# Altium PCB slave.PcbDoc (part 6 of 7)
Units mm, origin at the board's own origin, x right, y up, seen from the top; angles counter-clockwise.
Board outline 160 x 100 mm, 6 copper layers (Top, FUSED_VBAT-, Signals1, Signals2, SUPPLY, Bottom), stack 1.67 mm thick; 597 components, 381 nets, 1695 pads, 3028 vias.
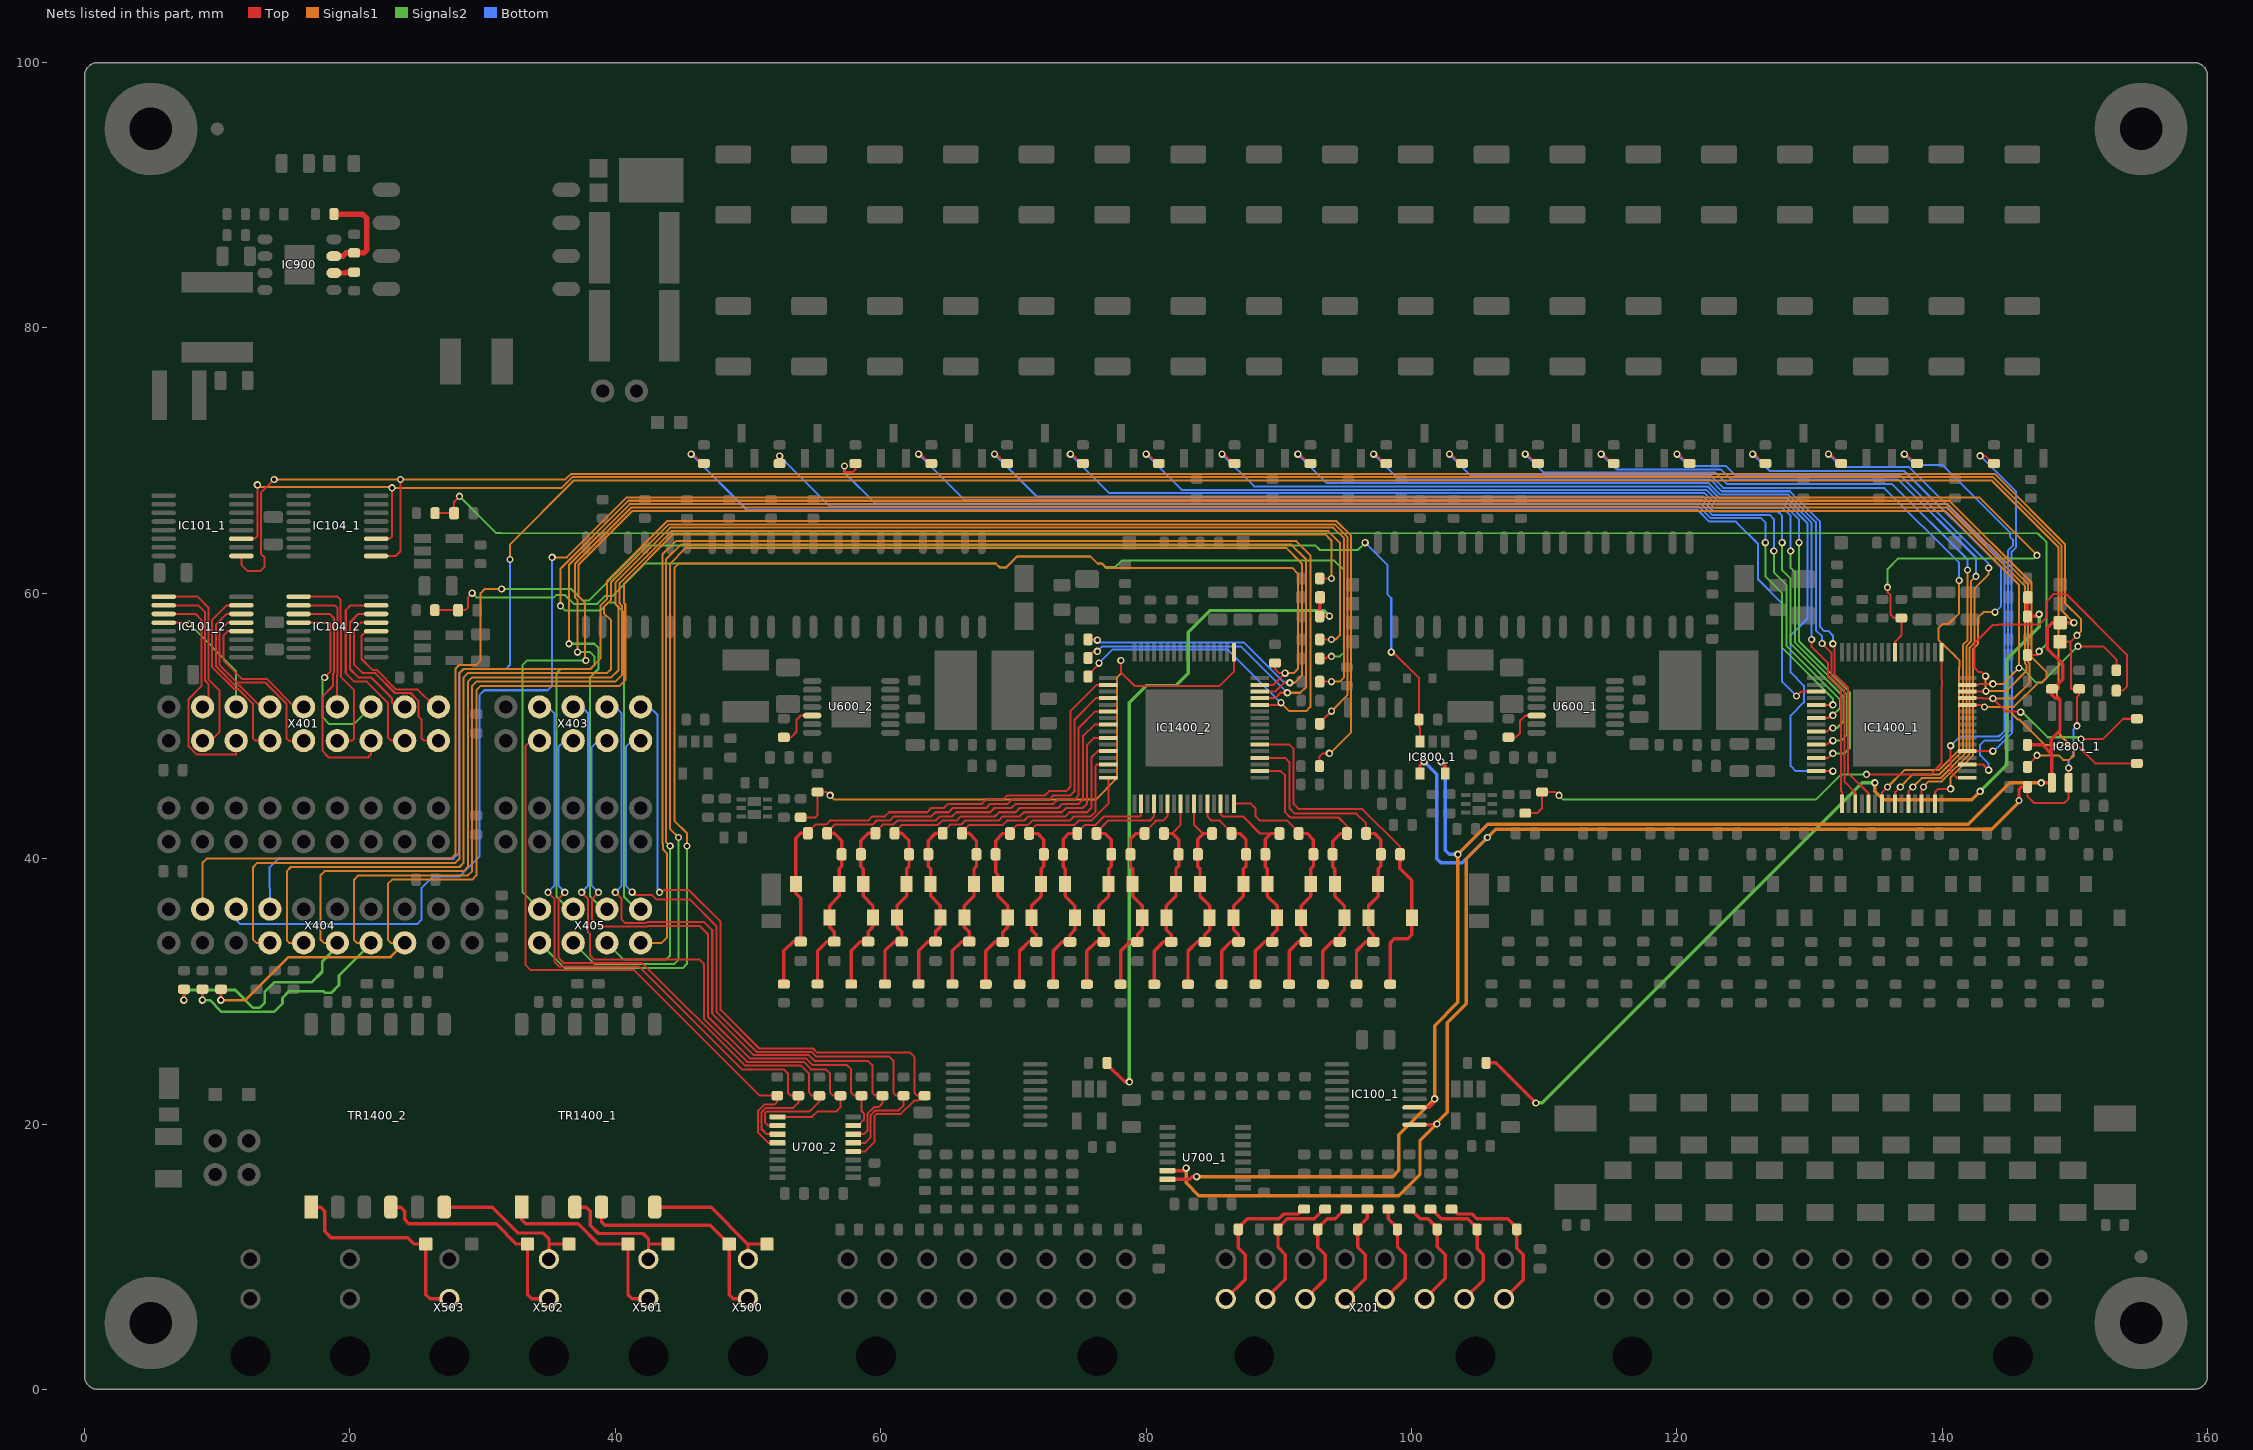
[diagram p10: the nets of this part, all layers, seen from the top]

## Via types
v1: diameter 0.55, hole 0.3, Top to Bottom, tented both sides, 2990 vias
v2: diameter 0.75, hole 0.5, Top to Bottom, tented both sides, 22 vias
v3: diameter 0.65, hole 0.4, Top to Bottom, tented both sides, 16 vias

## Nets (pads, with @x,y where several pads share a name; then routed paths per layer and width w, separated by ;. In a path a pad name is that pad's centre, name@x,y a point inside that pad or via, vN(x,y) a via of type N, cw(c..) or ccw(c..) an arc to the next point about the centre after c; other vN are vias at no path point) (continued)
PRIMARY-GPIO5-OPT: R1416_1.1 X404.13 | length 185.9
  Top w0.152: R1416_1.1@146.433,46.915 146.433,47.015 147.161,47.744 v1(147.161,47.784)
  Signals1 w0.152: v1(32.067,62.547) 32.067,63.691 36.876,68.499 143.748,68.499 148.76,63.487 148.76,52.77 148.671,52.681 148.671,52.221 148.887,52.005 148.887,49.318 149.906,48.299 149.843,48.299 149.906,48.236 149.906,47.776 149.582,47.452 149.122,47.452 148.79,47.784 v1(147.161,47.784)
  Bottom w0.152: X404.13@13.97,36.195 13.95,39.358 14.585,39.993 27.801,39.993 28.237,40.429 28.237,53.963 28.555,54.28 31.73,54.28 32.047,54.597 v1(32.067,62.547)
PRIMARY-GPIO6: IC1400_1.44 R1421_1.1 X405.1 | length 173.1
  Top w0.152: IC1400_1.44@141.958,51.598 143.03,51.598 v1(143.192,51.435) ; v1(148.844,48.578) 150.135,48.578 151.534,47.179 R1421_1.1@154.686,47.179
  Signals2 w0.152: v1(35.877,59.055) 36.241,58.691 38.857,58.691 39.458,59.292 39.917,59.292 40.64,58.569 40.64,37.148 41.593,36.195 X405.1@41.91,36.195
  Signals1 w0.152: v1(35.877,59.055) 35.877,61.869 40.984,66.975 140.548,66.975 146.746,60.778 146.746,55.186 147.854,54.078 147.854,53.618 147.53,53.294 147.272,53.294 145.414,51.435 144.748,51.435 ; v1(143.192,51.435) 144.748,51.435 ; v1(148.844,48.578) 147.744,48.578 145.832,50.49 145.693,50.49 144.748,51.435
PRIMARY-GPIO7: IC1400_1.45 R1422_1.1 X405.3 | length 168.9
  Top w0.152: IC1400_1.45@141.908,52.097 143.061,52.097 143.088,52.071 143.547,52.071 ; IC1400_1.45@141.958,52.097 IC1400_1.45@141.984,52.071 ; 143.548,52.071 v1@143.826,52.071 ; v1(143.827,52.07) 144.792,51.106 145.627,51.106 145.806,50.927 v1(145.923,51.044) ; v1(150.475,49.022) 152.148,49.022 153.67,50.544 R1422_1.1@154.686,50.544
  Signals2 w0.152: v1(36.512,56.197) 38.417,56.197 38.735,55.88 38.735,54.292 38.1,53.657 38.1,37.148 39.052,36.195 X405.3@39.37,36.195 ; v1(145.923,51.044) 146.062,51.044 147.957,49.149 150.348,49.149 v1(150.475,49.022)
  Signals1 w0.152: v1(36.512,56.197) 36.512,62.145 41.089,66.721 140.443,66.721 146.492,60.673 146.492,54.821 146.604,54.708 146.604,53.259 145.415,52.07 v1(143.827,52.07)
PRIMARY-GPIO8: IC1400_1.46 R1423_1.1 X405.5 | length 178.4
  Top w0.152: IC1400_1.46@141.958,52.598 143.29,52.598 v1(143.317,52.625) ; v1(143.29,53.751) 142.985,54.056 142.772,54.056 142.448,54.38 142.448,56.237 143.823,57.612 144.248,57.612 144.269,57.633 147.317,57.633 147.874,58.19 147.874,59.394 148.425,59.944 149.35,59.944 153.924,55.37 153.924,52.959 153.63,52.665 R1423_1.1@153.132,52.665
  Signals2 w0.152: X405.5@36.83,36.195 36.512,36.195 35.56,37.148 35.56,53.975 35.877,54.292 38.1,54.292 38.417,54.61 38.417,55.245 38.1,55.562 v1(37.148,55.562)
  Signals1 w0.152: v1(37.148,55.562) 37.148,59.499 36.974,59.673 36.974,62.247 41.194,66.467 140.338,66.467 146.238,60.568 146.238,54.716 146.35,54.603 146.35,54.143 144.832,52.625 v1(143.317,52.625) ; v1@143.29,52.598 143.29,52.934 143.273,52.951 143.273,53.41 143.29,53.427 v1(143.29,53.751)
PRIMARY-GPIO9: IC1400_1.47 R1424_1.1 X405.7 | length 164.7
  Top w0.152: IC1400_1.47@141.908,53.097 142.709,53.097 142.792,53.18 v1(143.827,53.18) ; v1(150.241,56.007) 152.144,56.007 153.132,55.019 R1424_1.1@153.132,54.199
  Signals2 w0.152: X405.7@34.29,36.195 33.02,37.465 33.02,54.61 33.337,54.927 v1(37.782,54.927) ; v1(145.796,54.373) 145.991,54.373 147.07,53.294 147.53,53.294 150.241,56.005 v1(150.241,56.007)
  Signals1 w0.152: v1(37.782,54.927) 37.702,55.008 37.702,59.304 37.228,59.778 37.228,62.142 41.299,66.213 140.232,66.213 145.796,60.65 v1(145.796,54.373) 144.603,53.18 v1(143.827,53.18)
PRIMARY-IN+: TP1405_1.1 TR1400_1.4 X500.1 | length 16.8
  Top w0.254: TR1400_1.4@38.961,13.738 38.961,12.633 39.211,12.383 47.161,12.383 TP1405_1.1@48.59,10.954 48.59,7.131 48.903,6.818 X500.1@50,6.818
PRIMARY-IN-: TP1404_1.1 TR1400_1.6 X500.2 | length 10.7
  Top w0.254: TR1400_1.6@43.068,13.738 47.216,13.738 50,10.954 ; X500.2@50,9.815 50,10.954 ; TP1404_1.1@51.435,10.954 50,10.954
PRIMARY-LTC-DRIVE: IC1400_1.49 R605_1.1 R610_1.2 | length 42.6
  Top w0.152: R605_1.1@108.585,43.432 109.472,43.432 109.855,43.815 R610_1.2@109.855,45.02 110.872,45.02 v1(111.125,44.767) ; v1(134.302,46.355) 139.14,46.355 139.958,47.173 139.958,52.981 140.012,53.035 140.012,53.495 139.958,53.549 IC1400_1.49@139.958,55.547 ; IC1400_1.49@139.958,55.598 IC1400_1.49@139.993,55.562
  Signals2 w0.152: v1(111.125,44.767) 111.443,44.45 111.76,44.45 130.493,44.45 132.398,46.355 v1(134.302,46.355)
PRIMARY-MUX-DATA_TEMP: C106_1.2 R108_1.2 R1409_1.1 | length 67.2
  Top w0.254: R108_1.2@105.634,24.606 106.362,24.606 v1(109.379,21.59) ; R1409_1.1@146.433,58.261 146.433,59.088 146.457,59.113 C106_1.2@146.457,59.69 ; R1409_1.1@146.483,58.261 147.154,58.261 147.173,58.281 v1(147.32,58.42)
  Signals2 w0.254: v1(109.379,21.59) 109.855,21.59 133.985,45.72 v1(134.938,45.72) ; v1(142.875,45.077) 144.882,47.084 144.882,55.029 147.32,57.468 v1(147.32,58.42)
  Signals1 w0.254: v1(134.938,45.72) 134.938,45.085 135.572,44.45 142.248,44.45 v1(142.875,45.077)
PRIMARY-MUX-DATA_USER: C107_1.2 R109_1.2 R1411_1.1 | length 133.5
  Top w0.152: R109_1.2@26.417,66.04 C107_1.2@27.85,66.04 27.85,66.903 v1(28.258,67.31) ; R1411_1.1@146.433,55.34 147.192,55.34 147.32,55.468 v1(147.32,55.626)
  Signals2 w0.152: v1(28.258,67.31) 31.039,64.528 31.432,64.528 147.191,64.516 147.874,63.833 147.874,56.18 v1(147.32,55.626)
PRIMARY-OUT+: TP1406_1.1 TR1400_1.1 X501.1 | length 15.2
  Top w0.254: TR1400_1.1@32.941,13.738 32.941,12.779 33.235,12.485 37.204,12.485 38.735,10.954 TP1406_1.1@40.957,10.954 40.957,7.144 41.283,6.818 X501.1@42.5,6.818
PRIMARY-OUT-: TP1407_1.1 TR1400_1.3 X501.2 | length 10.4
  Top w0.254: TR1400_1.3@37.048,13.434 37.048,13.738 37.809,13.738 38.112,13.434 38.112,12.37 38.735,11.747 42.088,11.747 42.5,11.335 42.5,10.954 ; X501.2@42.5,9.815 42.5,10.954 ; TP1407_1.1@43.974,10.954 42.5,10.954
PRIMARY-S1: IC1400_1.37 R1517.2 | length 27.4
  Top w0.152: IC1400_1.37@141.958,48.097 143.824,48.097 v1(143.827,48.101) ; v1(142.875,70.358) 143.245,70.358 143.818,69.785 R1517.2@143.918,69.785 ; R1517.2@144.045,69.785 R1517.2@144.145,69.785
  Bottom w0.152: v1(142.875,70.358) 145.588,67.645 145.588,63.483 145.242,63.136 145.242,54.143 145.287,54.098 145.287,49.487 143.901,48.101 v1(143.827,48.101)
PRIMARY-S2: IC1400_1.35 R1516.2 | length 33.4
  Top w0.152: v1(137.16,70.485) 137.313,70.485 138.013,69.785 R1516.2@138.112,69.785 ; IC1400_1.35@141.908,47.097 143.085,47.097 v1(143.51,46.672)
  Bottom w0.152: v1(137.16,70.485) 137.958,69.687 140.017,69.687 145.115,64.59 145.115,64.267 145.334,64.047 145.334,63.588 144.953,63.207 144.953,49.513 144.399,48.959 144.336,48.959 144.336,48.895 143.192,48.895 142.875,48.578 142.875,47.784 143.51,47.149 v1(143.51,46.672)
PRIMARY-S3: IC1400_1.33 R1515.2 | length 38.5
  Top w0.152: v1(131.445,70.485) 131.598,70.485 132.298,69.785 R1515.2@132.398,69.785 ; v1(140.653,48.509) 140.653,46.551 141.106,46.097 IC1400_1.33@141.908,46.097
  Bottom w0.152: v1(131.445,70.485) 132.398,69.532 137.477,69.532 144.699,62.311 144.699,49.618 144.375,49.293 144.294,49.293 144.294,49.212 141.356,49.212 v1(140.653,48.509)
PRIMARY-S4: IC1400_1.31 R1514.2 | length 44.5
  Top w0.152: v1(125.73,70.485) 125.883,70.485 126.583,69.785 R1514.2@126.682,69.785 ; IC1400_1.31@139.457,44.097 139.457,45.001 139.721,45.265 v1(140.653,45.265)
  Signals1 w0.152: v1(140.653,45.265) 140.653,46.125 142.335,47.807 142.335,55.806 142.716,56.187 142.716,58.179 143.122,58.584 143.981,58.584 v1(143.986,58.579)
  Bottom w0.152: v1(125.73,70.485) 127,69.215 137.16,69.215 144.445,61.93 144.445,59.038 v1(143.986,58.579)
PRIMARY-S5: IC1400_1.29 R1513.2 | length 48.9
  Top w0.152: v1(120.015,70.485) 120.168,70.485 120.868,69.785 R1513.2@120.968,69.785 ; IC1400_1.29@138.457,44.097 138.457,45.265 v1(138.595,45.402)
  Signals1 w0.152: v1(138.595,45.402) 139.012,45.819 139.988,45.819 142.081,47.913 142.081,55.911 142.43,56.261 142.43,60.357 143.51,61.436 v1(143.51,61.912)
  Bottom w0.152: v1(120.015,70.485) 120.903,69.597 123.709,69.597 124.409,68.897 136.835,68.897 143.51,62.223 v1(143.51,61.912)
PRIMARY-S6: IC1400_1.27 R1512.2 | length 54.2
  Top w0.152: v1(114.303,70.485) 114.453,70.485 115.153,69.785 R1512.2@115.252,69.785 ; IC1400_1.27@137.458,44.147 137.458,45.065 v1(137.795,45.402)
  Signals1 w0.152: v1(137.795,45.402) 138.466,46.073 139.883,46.073 141.827,48.018 141.827,56.017 142.177,56.366 142.177,60.896 v1(142.558,61.277)
  Bottom w0.152: v1(114.303,70.485) 115.445,69.343 123.329,69.343 124.091,68.581 131.446,68.581 131.447,68.58 136.674,68.58 142.558,62.697 v1(142.558,61.277)
PRIMARY-S7: IC1400_1.25 R1535.2 | length 59.8
  Top w0.152: v1(108.585,70.485) 108.738,70.485 109.438,69.785 R1535.2@109.537,69.785 ; IC1400_1.25@136.457,44.097 136.457,45.017 136.467,45.017 v1(136.852,45.402)
  Signals1 w0.152: v1(136.852,45.402) 137.805,46.355 139.805,46.355 141.573,48.123 141.573,56.122 141.922,56.471 v1(141.922,61.754)
  Bottom w0.152: v1(108.585,70.485) 109.981,69.089 122.936,69.089 123.775,68.25 136.22,68.25 141.922,62.547 v1(141.922,61.754)
PRIMARY-S8: IC1400_1.23 R1534.2 | length 66.8
  Top w0.152: v1(102.87,70.485) 103.023,70.485 103.723,69.785 R1534.2@103.822,69.785 ; IC1400_1.23@135.457,44.097 135.457,44.97 v1(135.89,45.402)
  Signals1 w0.152: v1(135.89,45.402) 137.16,46.672 139.763,46.672 141.287,48.197 141.287,54.417 141.319,54.449 141.319,54.908 141.019,55.208 141.019,55.238 140.44,55.816 140.411,55.816 139.717,56.51 139.717,57.36 140.042,57.684 140.483,57.684 141.287,58.489 v1(141.287,60.96)
  Bottom w0.152: v1(102.87,70.485) 104.52,68.835 122.617,68.835 123.507,67.945 130.822,67.945 130.835,67.933 135.656,67.933 141.287,62.301 v1(141.287,60.96)
PRIMARY-S9: IC1400_1.21 R1533.2 | length 60
  Top w0.152: v1(97.155,70.485) 97.308,70.485 98.008,69.785 R1533.2@98.108,69.785 ; v1(131.762,56.197) 131.903,56.057 131.903,53.913 132.905,52.91 132.905,46.482 134.457,44.93 IC1400_1.21@134.457,44.097
  Bottom w0.152: v1(97.155,70.485) 99.059,68.581 122.512,68.581 123.402,67.691 128.524,67.691 130.81,65.405 130.81,57.468 131.127,57.15 131.445,57.15 131.777,56.818 131.777,56.212 v1(131.762,56.197)
PRIMARY-S10: IC1400_1.19 R1532.2 | length 64.9
  Top w0.152: v1(91.44,70.485) 91.593,70.485 92.293,69.785 R1532.2@92.392,69.785 ; v1(130.964,56.212) 131.649,55.527 131.649,53.807 132.651,52.805 132.651,45.783 133.457,44.978 IC1400_1.19@133.457,44.097
  Bottom w0.152: v1(91.44,70.485) 93.616,68.309 122.425,68.309 123.297,67.437 128.419,67.437 130.493,65.363 130.493,57.226 130.964,56.755 v1(130.964,56.212)
PRIMARY-S11: IC1400_1.17 R1531.2 | length 70
  Top w0.152: v1(85.725,70.485) 85.878,70.485 86.578,69.785 R1531.2@86.677,69.785 ; v1(130.175,56.515) 130.175,55.971 131.395,54.751 131.395,53.702 132.398,52.7 132.398,45.085 132.457,45.025 IC1400_1.17@132.457,44.097
  Bottom w0.152: v1(85.725,70.485) 88.155,68.055 122.32,68.055 123.192,67.183 128.314,67.183 130.175,65.322 v1(130.175,56.515)
PRIMARY-S12: IC1400_1.15 R1530.2 | length 77.5
  Top w0.152: v1(80.01,70.485) 80.163,70.485 80.863,69.785 R1530.2@80.962,69.785 ; IC1400_1.15@130.457,46.598 v1(131.762,46.598)
  Bottom w0.152: v1(80.01,70.485) 82.694,67.801 122.215,67.801 123.087,66.929 128.208,66.929 129.857,65.28 129.857,58.102 128.588,56.832 128.588,54.038 129.586,53.04 129.586,51.774 128.588,50.775 128.588,46.99 128.98,46.598 v1(131.762,46.598)
PRIMARY-S13: IC1400_1.13 R1553.2 | length 79.9
  Top w0.152: v1(74.295,70.485) 74.448,70.485 75.148,69.785 R1553.2@75.248,69.785 ; IC1400_1.13@130.457,47.598 131.418,47.598 v1(131.762,47.942)
  Signals2 w0.152: v1(129.222,63.817) 129.222,56.366 133.079,52.51 133.079,48.375 132.646,47.942 v1(131.762,47.942)
  Bottom w0.152: v1(74.295,70.485) 77.233,67.547 122.11,67.547 122.981,66.675 128.103,66.675 129.222,65.556 v1(129.222,63.817)
PRIMARY-S14: IC1400_1.11 R1552.2 | length 84.1
  Top w0.152: v1(68.58,70.485) 68.733,70.485 69.433,69.785 R1552.2@69.532,69.785 ; IC1400_1.11@130.457,48.598 131.306,48.598 131.604,48.895 v1(131.762,48.895)
  Signals2 w0.152: v1(128.588,63.182) 128.588,61.912 128.905,61.595 128.905,56.324 132.825,52.404 132.825,49.322 132.398,48.895 v1(131.762,48.895)
  Bottom w0.152: v1(68.58,70.485) 71.772,67.293 122.004,67.293 122.876,66.421 127.998,66.421 128.588,65.831 v1(128.588,63.182)
PRIMARY-S15: IC1400_1.9 R1551.2 | length 88.1
  Top w0.152: v1(62.865,70.485) 63.018,70.485 63.718,69.785 R1551.2@63.817,69.785 ; IC1400_1.9@130.457,49.598 131.354,49.598 131.604,49.847 v1(131.762,49.847)
  Signals2 w0.152: v1(127.953,63.817) 127.953,61.744 128.588,61.109 128.588,56.197 132.571,52.214 132.571,50.338 132.08,49.847 v1(131.762,49.847)
  Bottom w0.152: v1(62.865,70.485) 66.311,67.039 121.899,67.039 122.771,66.167 127.635,66.167 127.953,65.849 v1(127.953,63.817)
PRIMARY-S16: IC1400_1.7 R1550.2 | length 92.3
  Top w0.152: v1(57.277,69.596) 57.277,69.151 57.921,69.151 58.102,69.333 R1550.2@58.102,69.785 ; IC1400_1.7@130.457,50.598 131.401,50.598 131.604,50.8 v1(131.762,50.8)
  Signals2 w0.152: v1(127.317,63.182) 127.317,61.595 128.27,60.642 128.27,56.039 132.317,51.992 132.317,51.354 v1(131.762,50.8)
  Bottom w0.152: v1(57.277,69.596) 57.277,69.088 59.58,66.785 121.794,66.785 122.666,65.913 127,65.913 127.317,65.596 v1(127.317,63.182)
PRIMARY-S17: IC1400_1.5 R1549.2 | length 94.1
  Top w0.152: R1549.2@52.387,69.785 v1(52.387,70.34) ; IC1400_1.5@130.457,51.598 131.759,51.598 v1(131.762,51.594)
  Signals2 w0.152: v1(126.682,63.817) 126.682,61.277 127.953,60.008 127.953,55.88 131.762,52.07 v1(131.762,51.594)
  Bottom w0.152: v1(52.387,70.34) 56.196,66.531 121.689,66.531 122.561,65.659 126.365,65.659 126.682,65.341 v1(126.682,63.817)
PRIMARY-S18: IC1400_1.3 R1548.2 | length 98.7
  Top w0.152: v1(45.72,70.485) 45.873,70.485 46.573,69.785 R1548.2@46.672,69.785 ; v1(129.032,52.254) 129.376,52.598 IC1400_1.3@130.457,52.598
  Bottom w0.152: v1(45.72,70.485) 49.928,66.277 121.584,66.277 122.455,65.405 124.46,65.405 126.128,63.737 126.128,61.048 127.953,59.223 127.953,53.333 v1(129.032,52.254)
PRIMARY-SCL: IC100_1.1 IC101_1.1 IC104_1.1 IC800_1.4 IC801_1.6 R1417_1.1 R1420_1.1 TP1409_1.1 U700_1.14 | length 287.4
  Top w0.152: IC101_1.1@11.786,62.801 IC101_1.1@11.815,62.801 ; IC101_1.1@11.815,62.813 IC101_1.1@11.815,62.801 ; v1(14.287,68.58) 13.886,68.178 13.889,68.175 13.283,67.568 13.283,62.984 13.572,62.695 13.572,62 13.247,61.676 12.3,61.676 11.815,62.161 IC101_1.1@11.815,62.801 ; IC104_1.1@21.946,62.801 IC104_1.1@21.975,62.801 ; IC104_1.1@21.975,62.813 23.443,62.813 23.812,63.182 v1(23.812,68.58) ; R1417_1.1@146.433,45.402 146.433,44.702 146.939,44.196 149.225,44.196 149.542,44.514 IC801_1.6@149.542,45.719 v1(149.542,46.831) ; TP1409_1.1@148.887,56.356 149.701,56.356 ; v1(150.177,50.006) 150.177,52.188 150.336,52.347 R1420_1.1@150.336,52.799 149.701,52.799 149.701,55.763 149.687,55.777 149.687,56.342 149.701,56.356 ; v1(150.177,56.832) 149.701,56.356
  Top w0.254: U700_1.14@81.605,16.488 82.845,16.488 v1(83.026,16.669) ; IC100_1.1@100.239,19.95 101.865,19.95 v1(101.917,20.002) ; IC800_1.4@100.65,46.425 100.65,46.993 v1(100.965,47.307) ; v1(145.8,44.379) 145.8,45.222 145.981,45.402 R1417_1.1@146.433,45.402
  Signals1 w0.152: v1(14.287,68.58) v1(23.812,68.58) 36.238,68.58 36.666,69.007 143.958,69.007 149.268,63.697 149.268,59.244 150.484,58.028 150.484,57.139 v1(150.177,56.832)
  Signals1 w0.254: v1(83.026,16.669) 83.026,15.557 83.979,14.605 99.06,14.605 100.647,16.192 100.647,18.732 v1(101.917,20.002) 101.917,20.099 102.711,20.893 102.711,27.622 104.14,29.051 104.14,40.005 v1(105.727,41.593) 106.362,42.227 106.68,42.227 143.736,42.227 145.8,44.291 v1(145.8,44.379)
  Bottom w0.152: v1(149.542,46.831) 149.542,47.412 149.906,47.776 149.906,49.735 v1(150.177,50.006)
  Bottom w0.254: v1(100.965,47.307) 101.917,46.355 101.917,40.005 102.235,39.688 103.822,39.688 v1(105.727,41.593)
PRIMARY-SDA: IC100_1.3 IC101_1.3 IC104_1.3 IC800_1.5 IC801_1.5 R1415_1.1 R1419_1.1 TP1408_1.1 U700_1.15 | length 273.5
  Top w0.152: IC101_1.3@11.815,64.113 12.842,64.113 13.018,64.288 v1(13.018,68.178) ; IC104_1.3@21.975,64.113 23.002,64.113 23.177,64.288 v1(23.177,67.945)
  Top w0.254: U700_1.15@81.605,15.838 83.306,15.838 83.502,16.034 v1(83.82,16.034) ; IC100_1.3@100.239,21.25 101.357,21.25 101.702,21.595 101.702,21.843 v1(101.759,21.9) ; v1(102.235,47.307) 102.55,46.992 IC800_1.5@102.55,46.425 ; R1415_1.1@146.433,48.578 147.574,48.578 148.239,47.913 ; v1(147.476,45.719) IC801_1.5@148.273,45.719 148.273,47.879 148.239,47.913 ; v1(149.93,57.785) TP1408_1.1@148.907,57.785 148.306,57.785 147.935,57.414 147.935,55.836 149.098,54.673 149.098,53.524 148.372,52.799 R1419_1.1@148.273,52.799 148.273,52.347 148.522,52.097 148.723,52.097 148.887,51.933 148.887,49.634 148.239,48.985 148.239,47.913
  Signals1 w0.152: v1(13.018,68.178) 13.17,68.026 23.097,68.026 v1(23.177,67.945) 35.963,67.945 36.771,68.753 143.853,68.753 149.014,63.592 149.014,58.7 v1(149.93,57.785)
  Signals1 w0.254: v1(83.82,16.034) 98.584,16.034 99.06,16.51 99.06,19.201 v1(101.759,21.9) 101.759,27.416 103.505,29.163 v1(103.505,40.322) 105.766,42.583 106.68,42.583 141.961,42.583 145.096,45.719 v1(147.476,45.719)
  Bottom w0.254: v1(102.235,47.307) 102.552,46.99 102.552,40.64 102.87,40.322 v1(103.505,40.322)
PRIMARY-T-SENSOR_0: R107_1.1 R112_1.2 X201.1 | length 11.6
  Top w0.254: R112_1.2@103.029,13.588 103.129,13.588 103.499,13.217 104.576,13.217 104.934,12.859 107.255,12.859 107.953,12.161 R107_1.1@107.953,12.061 107.953,10.633 108.426,10.16 108.426,8.254 X201.1@106.99,6.818
PRIMARY-T-SENSOR_1: R106_1.1 R113_1.2 X201.2 | length 10.2
  Top w0.254: R113_1.2@101.441,13.588 101.541,13.588 102.27,12.859 104.255,12.859 104.953,12.161 R106_1.1@104.953,12.061 104.953,10.617 105.41,10.16 105.41,8.235 X201.2@103.993,6.818
PRIMARY-T-SENSOR_2: R105_1.1 R114_1.2 X201.3 | length 8.9
  Top w0.254: R114_1.2@99.854,13.588 99.954,13.588 100.683,12.859 101.255,12.859 101.953,12.161 R105_1.1@101.953,12.061 101.953,10.759 102.552,10.16 102.552,8.374 X201.3@100.996,6.818
PRIMARY-T-SENSOR_3: R104_1.1 R115_1.2 X201.4 | length 7.9
  Top w0.254: X201.4@97.999,6.818 99.536,8.355 99.536,10.16 98.953,10.743 R104_1.1@98.953,12.061 98.953,12.161 98.266,12.848 R115_1.2@98.266,13.588
PRIMARY-T-SENSOR_4: R103_1.1 R116_1.2 X201.5 | length 7.9
  Top w0.254: X201.5@95.001,6.818 96.52,8.337 96.52,10.16 95.953,10.727 R103_1.1@95.953,12.061 95.953,12.161 96.679,12.886 R116_1.2@96.679,13.588
PRIMARY-T-SENSOR_5: R102_1.1 R117_1.2 X201.6 | length 8.9
  Top w0.254: X201.6@92.004,6.818 93.504,8.318 93.504,10.16 92.953,10.711 R102_1.1@92.953,12.061 92.953,12.161 93.651,12.859 94.262,12.859 94.991,13.588 R117_1.2@95.091,13.588
PRIMARY-T-SENSOR_6: R101_1.1 R118_1.2 X201.7 | length 10.3
  Top w0.254: X201.7@89.007,6.818 90.487,8.299 90.487,10.16 89.953,10.694 R101_1.1@89.953,12.061 89.953,12.161 90.651,12.859 92.675,12.859 93.404,13.588 R118_1.2@93.504,13.588
PRIMARY-T-SENSOR_7: R100_1.1 R119_1.2 X201.8 | length 11.7
  Top w0.254: X201.8@86.01,6.818 87.471,8.279 87.471,10.16 86.953,10.678 R100_1.1@86.953,12.061 86.953,12.161 87.651,12.859 90.011,12.859 90.369,13.217 91.446,13.217 91.816,13.588 R119_1.2@91.916,13.588
PRIMARY-TEMP-ALERT: IC800_1.3 R800_1.1 X404.17 | length 130.1
  Top w0.152: v1(98.485,55.562) 98.614,55.562 100.582,53.594 R800_1.1@100.582,50.482 100.582,49.931 100.65,49.863 IC800_1.3@100.65,48.825
  Signals2 w0.152: v1(31.432,60.325) 36.681,60.325 37.553,59.453 38.012,59.453 42.169,63.61 92.769,63.61 93.115,63.263 95.966,63.263 v1(96.52,63.817)
  Signals1 w0.152: X404.17@8.89,36.195 8.89,39.688 9.207,40.005 27.622,40.005 27.94,40.322 27.94,54.292 28.258,54.61 29.527,54.61 29.845,54.927 29.845,60.008 30.162,60.325 v1(31.432,60.325)
  Bottom w0.152: v1(96.52,63.817) 98.188,62.149 98.188,59.927 98.485,59.63 v1(98.485,55.562)
PRIMARY-WDT: IC1400_1.56 R1404_1.1 X404.15 | length 184.9
  Top w0.152: v1(135.89,60.452) 135.89,60.092 136.124,59.859 136.124,58.38 136.136,58.38 136.378,58.137 R1404_1.1@136.93,58.137 136.93,56.821 136.458,56.349 IC1400_1.56@136.458,55.547
  Signals2 w0.152: v1(135.89,60.452) 135.89,61.821 136.694,62.626 146.922,62.626 v1(147.161,62.865)
  Signals1 w0.152: v1(35.242,62.706) 36.355,62.706 40.879,67.229 142.797,67.229 v1(147.161,62.865)
  Bottom w0.152: X404.15@11.43,36.195 11.41,35.389 11.727,35.071 25.062,35.071 25.38,35.389 25.38,37.77 26.269,38.659 28.263,38.659 29.761,40.157 29.761,52.312 30.142,52.693 34.905,52.693 35.222,53.01 35.242,53.03 v1(35.242,62.706)
R_FB: IC900.6 R904.1 | length 1.6
  Top w0.406: IC900.6@18.794,84.138 19.703,84.138 19.768,84.203 R904.1@20.32,84.203
R_REF: IC900.7 R902.2 R905.2 | length 7.7
  Top w0.406: IC900.7@18.794,85.407 19.467,85.407 19.72,85.66 R902.2@20.32,85.66 21.06,85.66 21.273,85.873 21.273,88.265 20.955,88.582 R905.2@18.797,88.582
RON_1: R600_1.1 U600_1.5 | length 3.4
  Top w0.152: R600_1.1@107.315,49.147 107.867,49.147 108.186,49.467 108.186,50.401 108.57,50.785 U600_1.5@109.445,50.785
RON_2: R600_2.1 U600_2.5 | length 3.4
  Top w0.152: R600_2.1@52.705,49.147 53.257,49.147 53.657,49.548 53.657,50.482 53.96,50.785 U600_2.5@54.835,50.785
SECONDARY-ANALOG-IN_0: IC104_2.4 X401.1 | length 10.3
  Top w0.152: IC104_2.4@21.975,57.143 21.225,57.143 20.872,56.79 20.872,55.046 21.69,54.229 22.013,54.229 23.5,52.742 25.116,52.742 26.422,51.435 X401.1@26.67,51.435
SECONDARY-ANALOG-IN_1: IC104_2.5 X401.2 | length 14.8
  Top w0.152: IC104_2.5@21.975,57.793 20.804,57.793 20.32,57.309 20.32,54.61 20.955,53.975 21.907,53.975 23.395,52.488 24.566,52.488 25.183,51.871 25.183,50.7 25.4,50.482 25.4,49.054 25.559,48.895 X401.2@26.67,48.895
SECONDARY-ANALOG-IN_2: IC104_2.6 X401.3 | length 11.2
  Top w0.152: IC104_2.6@21.975,58.443 20.647,58.443 20.002,57.798 20.002,54.292 20.637,53.657 21.59,53.657 23.177,52.07 23.177,51.752 23.495,51.435 X401.3@24.13,51.435
SECONDARY-ANALOG-IN_3: IC104_2.7 X401.4 | length 15.2
  Top w0.152: IC104_2.7@21.946,59.093 20.041,59.093 19.685,58.737 19.685,53.975 20.32,53.34 21.273,53.34 22.86,51.752 22.86,49.149 23.114,48.895 X401.4@24.13,48.895
SECONDARY-ANALOG-IN_4: IC104_2.12 X401.5 | length 14.1
  Top w0.152: IC104_2.12@16.125,57.793 18.407,57.793 18.55,57.65 18.55,54.11 v1(18.098,53.657)
  Signals2 w0.152: v1(18.098,53.657) 17.939,53.499 17.939,50.641 18.415,50.165 20.32,50.165 X401.5@21.59,51.435
SECONDARY-ANALOG-IN_5: IC104_2.11 X401.6 | length 18.2
  Top w0.152: IC104_2.11@16.125,58.443 18.463,58.443 18.796,58.109 18.796,57.763 18.804,57.755 18.804,54.005 18.72,53.921 18.72,53.01 17.939,52.229 17.939,48.101 18.415,47.625 21.361,47.625 21.59,47.854 X401.6@21.59,48.895
SECONDARY-ANALOG-IN_6: IC104_2.10 X401.7 | length 10.5
  Top w0.152: IC104_2.10@16.125,59.093 18.854,59.093 19.05,58.896 19.05,57.868 19.058,57.86 19.058,53.9 19.012,53.853 19.012,51.473 X401.7@19.05,51.435
SECONDARY-ANALOG-IN_7: IC104_2.9 X401.8 | length 15.5
  Top w0.152: IC104_2.9@16.125,59.743 19.072,59.743 19.304,59.51 19.304,57.974 19.312,57.966 19.312,53.794 19.304,53.786 19.304,53.721 20.32,52.705 20.32,49.054 20.161,48.895 X401.8@19.05,48.895
SECONDARY-ANALOG-IN_8: IC101_2.4 X401.9 | length 10.9
  Top w0.152: IC101_2.4@11.815,57.143 10.788,57.143 10.477,56.832 10.477,54.927 11.857,53.548 13.73,53.548 15.855,51.423 X401.9@16.51,51.435
SECONDARY-ANALOG-IN_9: IC101_2.5 X401.10 | length 14.7
  Top w0.152: IC101_2.5@11.815,57.793 10.788,57.793 10.16,57.164 10.16,54.61 11.476,53.294 13.6,53.294 15.22,51.674 15.22,49.074 15.413,48.881 X401.10@16.51,48.895
SECONDARY-ANALOG-IN_10: IC101_2.6 X401.11 | length 10.7
  Top w0.152: IC101_2.6@11.815,58.443 10.71,58.443 9.906,57.639 9.906,54.505 11.371,53.04 11.698,53.04 13.315,51.423 X401.11@13.97,51.435
SECONDARY-ANALOG-IN_11: IC101_2.7 X401.12 | length 14.4
  Top w0.152: IC101_2.7@11.786,59.093 10.71,59.093 9.588,57.971 9.588,54.463 11.266,52.786 11.568,52.786 12.68,51.674 12.68,49.074 12.859,48.895 X401.12@13.97,48.895
SECONDARY-ANALOG-IN_12: IC101_2.12 X401.13 | length 9.7
  Top w0.152: IC101_2.12@5.965,57.793 7.772,57.793 v1(7.874,57.691)
  Signals2 w0.152: v1(7.874,57.691) 11.43,54.135 X401.13@11.43,51.435
SECONDARY-ANALOG-IN_13: IC101_2.11 X401.14 | length 17.9
  Top w0.152: IC101_2.11@5.965,58.443 8.359,58.443 8.826,57.975 8.826,53.023 7.837,52.033 7.837,48.459 8.454,47.842 11.418,47.842 11.43,47.854 X401.14@11.43,48.895
SECONDARY-ANALOG-IN_14: IC101_2.10 X401.15 | length 10.8
  Top w0.152: IC101_2.10@5.994,59.093 8.572,59.093 9.08,58.585 9.08,53.425 9.335,53.171 9.335,51.88 X401.15@8.89,51.435 X401.15@8.852,51.473
SECONDARY-ANALOG-IN_15: IC101_2.9 X401.16 | length 15
  Top w0.152: IC101_2.9@5.965,59.743 8.52,59.743 9.335,58.928 9.335,53.53 10.16,52.705 10.16,49.53 9.525,48.895 X401.16@8.89,48.895
SECONDARY-C0: C1311_2.2 IC1400_2.38 R1306_2.2 Z1305_2.2 | length 28.1
  Top w0.152: IC1400_2.38@88.618,48.598 90.805,48.598 91.123,48.28 91.123,44.133 91.518,43.737 96.312,43.737 99.15,40.899 C1311_2.2@99.15,40.322
  Top w0.254: R1306_2.2@98.405,30.583 98.405,33.643 98.722,33.96 99.722,33.96 100.04,34.278 100.04,38.358 99.13,39.268 99.13,39.726 99.15,39.746 C1311_2.2@99.15,40.322
SECONDARY-C1: C1305_2.1 C1310_2.2 C1311_2.1 IC1400_2.36 R1305_2.2 Z1304_2.2 Z1305_2.1 | length 26.3
  Top w0.152: IC1400_2.36@88.618,47.598 90.487,47.598 90.805,47.28 90.805,43.815 91.222,43.398 95.858,43.398 96.59,42.666 C1310_2.2@96.59,41.898
  Top w0.254: R1305_2.2@95.865,30.533 95.865,33.039 96.558,33.733 C1305_2.1@97.135,33.733 ; C1310_2.2@96.59,41.898 97.223,41.898 97.7,41.42 C1311_2.1@97.7,40.322 97.7,39.436 97.5,39.236 Z1304_2.2@97.5,38.088 97.5,37.183 96.77,36.453 96.77,34.643 97.135,34.278 C1305_2.1@97.135,33.872
SECONDARY-C2: C1304_2.1 C1309_2.2 C1310_2.1 IC1400_2.34 R1304_2.2 Z1303_2.2 Z1304_2.1 | length 23.8
  Top w0.152: IC1400_2.34@88.618,46.598 90.17,46.598 90.487,46.28 90.487,43.497 90.881,43.104 94.51,43.104 95.14,42.474 C1310_2.1@95.14,41.898
  Top w0.254: R1304_2.2@93.325,30.533 93.325,33.039 94.018,33.733 C1304_2.1@94.595,33.733 ; C1304_2.1@94.595,33.872 94.595,34.278 94.96,34.643 94.96,36.453 94.23,37.183 Z1304_2.1@94.23,38.088 94.23,39.236 94.07,39.396 C1309_2.2@94.07,40.322 94.07,41.304 94.663,41.898 C1310_2.1@95.14,41.898
SECONDARY-C3: C1303_2.1 C1308_2.2 C1309_2.1 IC1400_2.32 R1303_2.2 Z1302_2.2 Z1303_2.1 | length 19.6
  Top w0.152: IC1400_2.32@86.618,44.147 87.897,44.147 88.265,43.78 88.265,43.18 88.582,42.862 90.645,42.862 91.51,41.998 C1308_2.2@91.51,41.898
  Top w0.254: R1303_2.2@90.785,30.533 90.785,33.039 91.478,33.733 C1303_2.1@92.055,33.733 ; C1308_2.2@91.65,41.898 92.143,41.898 92.6,41.44 92.6,40.919 92.62,40.899 C1309_2.1@92.62,40.322 92.62,39.436 92.42,39.236 Z1302_2.2@92.42,38.088 92.42,37.183 91.69,36.453 91.69,34.643 92.055,34.278 C1303_2.1@92.055,33.872
SECONDARY-C4: C1302_2.1 C1307_2.2 C1308_2.1 IC1400_2.30 R1302_2.2 Z1301_2.2 Z1302_2.1 | length 18.6
  Top w0.152: IC1400_2.30@85.618,44.147 85.618,43.346 85.783,43.18 87.312,43.18 88.595,41.898 89.428,41.898
  Top w0.254: R1302_2.2@88.245,30.533 88.245,33.039 88.938,33.733 C1302_2.1@89.515,33.733 ; C1302_2.1@89.515,33.872 89.515,34.278 89.88,34.643 89.88,36.453 89.15,37.183 Z1302_2.1@89.15,38.088 89.15,39.236 88.99,39.396 C1307_2.2@88.99,40.322 88.99,41.46 89.428,41.898 C1308_2.1@90.06,41.898
SECONDARY-C5: C1301_2.1 C1306_2.2 C1307_2.1 IC1400_2.28 R1301_2.2 Z1300_2.2 Z1301_2.1 | length 16.6
  Top w0.152: IC1400_2.28@84.618,44.097 84.618,43.18 84.935,42.862 85.565,42.862 86.43,41.998 C1306_2.2@86.43,41.898
  Top w0.254: R1301_2.2@85.705,30.533 85.705,33.039 86.398,33.733 C1301_2.1@86.975,33.733 ; C1306_2.2@86.57,41.898 87.063,41.898 87.54,41.42 C1307_2.1@87.54,40.322 87.54,39.436 87.34,39.236 Z1300_2.2@87.34,38.088 87.34,37.376 87.34,37.183 86.61,36.453 86.61,34.643 86.975,34.278 C1301_2.1@86.975,33.872
SECONDARY-C6: C1300_2.1 C1306_2.1 C1323_2.2 IC1400_2.26 R1300_2.2 Z1300_2.1 Z1311_2.2 | length 15.8
  Top w0.152: IC1400_2.26@83.618,44.097 83.618,42.545 84.265,41.898
  Top w0.254: R1300_2.2@83.165,30.533 83.165,33.039 83.858,33.733 C1300_2.1@84.435,33.733 ; 84.265,41.898 84.348,41.898 ; C1300_2.1@84.435,33.872 84.435,34.278 84.8,34.643 84.8,36.453 84.07,37.183 Z1300_2.1@84.07,38.088 84.07,39.236 83.91,39.396 C1323_2.2@83.91,40.322 83.91,41.46 84.348,41.898 ; C1306_2.1@84.84,41.898 84.348,41.898
SECONDARY-C7: C1317_2.1 C1322_2.2 C1323_2.1 IC1400_2.24 R1312_2.2 Z1310_2.2 Z1311_2.1 | length 15.8
  Top w0.152: 81.97,41.898 82.618,42.545 IC1400_2.24@82.618,44.097
  Top w0.254: R1312_2.2@80.625,30.533 80.625,33.039 81.318,33.733 C1317_2.1@81.895,33.733 ; C1322_2.2@81.49,41.898 81.97,41.898 82.46,41.408 C1323_2.1@82.46,40.322 82.46,39.436 82.26,39.236 Z1310_2.2@82.26,38.088 82.26,37.183 81.53,36.453 81.53,34.643 81.895,34.278 C1317_2.1@81.895,33.872
SECONDARY-C8: C1316_2.1 C1321_2.2 C1322_2.1 IC1400_2.22 R1311_2.2 Z1309_2.2 Z1310_2.1 | length 16.6
  Top w0.152: C1322_2.1@79.76,41.898 C1322_2.1@79.83,41.967 ; C1322_2.1@79.9,41.898 79.9,41.998 80.725,42.823 80.725,42.862 81.3,42.862 81.618,43.18 IC1400_2.22@81.618,44.097
  Top w0.254: R1311_2.2@78.085,30.533 78.085,33.039 78.778,33.733 C1316_2.1@79.355,33.733 ; C1316_2.1@79.355,33.872 79.355,34.278 79.72,34.643 79.72,36.453 78.99,37.183 78.99,37.376 Z1310_2.1@78.99,38.088 78.99,39.236 78.83,39.396 C1321_2.2@78.83,40.322 78.83,41.46 79.268,41.898 C1322_2.1@79.76,41.898
SECONDARY-C9: C1315_2.1 C1320_2.2 C1321_2.1 IC1400_2.20 R1310_2.2 Z1308_2.2 Z1309_2.1 | length 19.2
  Top w0.152: C1320_2.2@76.27,41.898 76.27,41.998 77.135,42.862 80.3,42.862 80.618,43.18 IC1400_2.20@80.618,44.097
  Top w0.254: R1310_2.2@75.545,30.533 75.545,33.039 76.238,33.733 C1315_2.1@76.815,33.733 ; C1320_2.2@76.41,41.898 76.903,41.898 77.38,41.42 C1321_2.1@77.38,40.322 77.38,39.436 77.18,39.236 Z1308_2.2@77.18,38.088 77.18,37.376 77.18,37.183 76.45,36.453 76.45,34.643 76.815,34.278 C1315_2.1@76.815,33.872
SECONDARY-C10: C1314_2.1 C1319_2.2 C1320_2.1 IC1400_2.18 R1309_2.2 Z1307_2.2 Z1308_2.1 | length 19.5
  Top w0.152: C1320_2.1@74.82,41.898 74.82,41.998 75.373,42.55 76.205,42.55 76.835,43.18 79.534,43.18 79.618,43.264 IC1400_2.18@79.618,44.097
  Top w0.254: R1309_2.2@73.005,30.533 73.005,33.039 73.698,33.733 C1314_2.1@74.275,33.733 ; C1314_2.1@74.275,33.872 74.275,34.278 74.64,34.643 74.64,36.453 73.91,37.183 73.91,37.376 Z1308_2.1@73.91,38.088 73.91,39.236 73.75,39.396 C1319_2.2@73.75,40.322 73.75,41.46 74.188,41.898 C1320_2.1@74.68,41.898
SECONDARY-C11: C1313_2.1 C1318_2.2 C1319_2.1 IC1400_2.16 R1308_2.2 Z1306_2.2 Z1307_2.1 | length 22.2
  Top w0.152: C1318_2.2@71.19,41.898 71.19,41.998 71.743,42.55 74.618,42.55 74.93,42.862 75.882,42.862 77.168,44.148 IC1400_2.16@77.168,46.097
  Top w0.254: R1308_2.2@70.465,30.533 70.465,33.039 71.158,33.733 C1313_2.1@71.735,33.733 ; C1318_2.2@71.33,41.898 71.823,41.898 72.3,41.42 C1319_2.1@72.3,40.322 72.3,39.436 72.1,39.236 Z1306_2.2@72.1,38.088 72.1,37.183 71.37,36.453 71.37,34.643 71.735,34.278 C1313_2.1@71.735,33.872
SECONDARY-C12: C1312_2.1 C1318_2.1 C1335_2.2 IC1400_2.14 R1307_2.2 Z1306_2.1 Z1317_2.2 | length 25.1
  Top w0.152: C1318_2.1@69.74,41.898 69.74,41.998 70.293,42.55 71.12,42.55 71.432,42.862 74.253,42.862 74.571,43.18 75.841,43.18 76.2,43.539 76.2,46.99 76.307,47.097 IC1400_2.14@77.117,47.097
  Top w0.254: R1307_2.2@67.925,30.533 67.925,33.039 68.618,33.733 C1312_2.1@69.195,33.733 69.195,34.463 69.58,34.848 Z1317_2.2@69.58,35.56 69.58,36.465 68.83,37.215 68.83,37.376 Z1306_2.1@68.83,38.088 68.83,38.799 68.67,38.959 68.67,40.005 68.67,41.365 69.203,41.898 C1318_2.1@69.74,41.898
SECONDARY-C13: C1329_2.1 C1334_2.2 C1335_2.1 IC1400_2.12 R1318_2.2 Z1316_2.2 Z1317_2.1 | length 29.1
  Top w0.152: C1334_2.2@66.13,41.91 66.13,42.01 66.665,42.545 69.215,42.545 69.532,42.862 70.802,42.862 71.12,43.18 73.936,43.18 74.253,43.497 75.565,43.497 75.882,43.815 75.882,47.625 76.355,48.097 IC1400_2.12@77.117,48.097
  Top w0.254: R1318_2.2@65.405,30.545 65.405,33.052 66.098,33.745 C1329_2.1@66.675,33.745 66.675,34.483 66.31,34.848 Z1317_2.1@66.31,35.56 66.31,36.465 67.04,37.195 67.04,37.388 Z1316_2.2@67.04,38.1 67.04,39.248 67.22,39.428 67.22,40.005 67.22,41.365 66.675,41.91 C1334_2.2@66.358,41.91
SECONDARY-C14: C1328_2.1 C1333_2.2 C1334_2.1 IC1400_2.10 R1317_2.2 Z1315_2.2 Z1316_2.1 | length 31.5
  Top w0.152: C1334_2.1@64.68,41.91 64.68,42.01 65.233,42.563 66.058,42.563 66.358,42.862 68.897,42.862 69.215,43.18 70.485,43.18 70.802,43.497 73.66,43.497 73.977,43.815 75.248,43.815 75.565,44.133 75.565,48.578 76.085,49.097 IC1400_2.10@77.117,49.097
  Top w0.254: R1317_2.2@62.865,30.545 62.865,33.052 63.558,33.745 C1328_2.1@64.135,33.745 64.135,34.483 64.5,34.848 Z1315_2.2@64.5,35.56 64.5,36.465 63.77,37.195 Z1316_2.1@63.77,38.1 63.77,39.248 63.59,39.428 63.59,40.005 63.59,41.365 64.135,41.91 C1334_2.1@64.54,41.91
SECONDARY-C15: C1327_2.1 C1332_2.2 C1333_2.1 IC1400_2.8 R1316_2.2 Z1314_2.2 Z1315_2.1 | length 35.7
  Top w0.152: C1332_2.2@61.05,41.91 61.05,42.01 61.442,42.402 61.452,42.402 61.595,42.545 64.323,42.545 64.641,42.862 65.732,42.862 66.049,43.18 68.622,43.18 68.939,43.497 70.168,43.497 70.485,43.815 73.384,43.815 73.702,44.133 74.93,44.133 75.248,44.45 75.248,49.212 76.132,50.097 IC1400_2.8@77.117,50.097
  Top w0.254: R1316_2.2@60.325,30.545 60.325,33.052 61.018,33.745 C1327_2.1@61.595,33.745 61.595,34.483 61.23,34.848 Z1315_2.1@61.23,35.56 61.23,36.465 61.96,37.195 Z1314_2.2@61.96,38.1 61.96,39.248 62.14,39.428 62.14,40.005 62.14,41.365 61.595,41.91 C1332_2.2@61.19,41.91
SECONDARY-C16: C1326_2.1 C1331_2.2 C1332_2.1 IC1400_2.6 R1315_2.2 Z1313_2.2 Z1314_2.1 | length 37.7
  Top w0.152: C1332_2.1@59.6,41.91 59.6,42.01 60.153,42.563 60.96,42.563 61.26,42.862 64.135,42.862 64.453,43.18 65.405,43.18 65.722,43.497 68.263,43.497 68.58,43.815 69.85,43.815 70.168,44.133 73.025,44.133 73.343,44.45 74.612,44.45 74.93,44.767 74.93,49.847 76.18,51.097 IC1400_2.6@77.117,51.097
  Top w0.254: R1315_2.2@57.785,30.545 57.785,33.052 58.478,33.745 C1326_2.1@59.055,33.745 59.055,34.483 59.42,34.848 Z1313_2.2@59.42,35.56 59.42,36.465 58.69,37.195 Z1314_2.1@58.69,38.1 58.69,39.248 58.51,39.428 58.51,40.005 58.51,41.365 59.055,41.91 C1332_2.1@59.46,41.91
SECONDARY-C17: C1325_2.1 C1330_2.2 C1331_2.1 IC1400_2.4 R1314_2.2 Z1312_2.2 Z1313_2.1 | length 42
  Top w0.152: C1330_2.2@55.97,41.91 55.97,42.01 56.523,42.563 59.39,42.563 59.69,42.862 60.684,42.862 61.002,43.18 63.817,43.18 64.135,43.497 65.129,43.497 65.447,43.815 67.945,43.815 68.263,44.133 69.574,44.133 69.892,44.45 72.707,44.45 73.025,44.767 74.295,44.767 74.612,45.085 74.612,50.482 76.227,52.097 IC1400_2.4@77.117,52.097
  Top w0.254: R1314_2.2@55.245,30.545 55.245,33.052 55.938,33.745 C1325_2.1@56.515,33.745 56.515,34.483 56.15,34.848 Z1313_2.1@56.15,35.56 56.15,36.465 56.88,37.195 Z1312_2.2@56.88,38.1 56.88,39.248 57.06,39.428 57.06,40.005 57.06,41.365 56.515,41.91 C1330_2.2@56.11,41.91
SECONDARY-C18: C1324_2.1 C1330_2.1 IC1400_2.2 R1313_2.2 Z1312_2.1 | length 43.6
  Top w0.152: C1330_2.1@54.52,41.91 54.52,42.01 55.073,42.563 55.898,42.563 56.197,42.862 59.055,42.862 59.372,43.18 60.325,43.18 60.642,43.497 63.5,43.497 63.817,43.815 64.77,43.815 65.087,44.133 67.627,44.133 67.945,44.45 69.215,44.45 69.532,44.767 72.39,44.767 72.707,45.085 73.977,45.085 74.295,45.402 74.295,51.117 76.275,53.097 IC1400_2.2@77.117,53.097
  Top w0.254: R1313_2.2@52.705,30.545 52.705,33.052 53.398,33.745 C1324_2.1@53.975,33.745 53.975,37.023 53.61,37.388 Z1312_2.1@53.61,38.1 53.61,41.545 53.975,41.91 C1330_2.1@54.38,41.91
SECONDARY-DIGITAL-IO_0: R700_2.1 U700_2.4 X403.1 | length 55.1
  Top w0.152: v1(43.339,37.465) 43.503,37.465 43.656,37.619 45.554,37.631 47.942,35.242 47.942,28.607 50.857,25.693 54.903,25.693 55.195,25.4 62.198,25.4 62.544,25.054 62.544,22.357 62.766,22.135 R700_2.1@63.217,22.135 ; U700_2.4@57.936,17.931 58.638,17.931 58.645,17.939 58.84,17.939 59.531,18.63 59.531,20.586 59.71,20.764 61.528,20.764 62.528,21.765 62.847,21.765 R700_2.1@63.217,22.135 ; R700_2.1@63.317,22.135 R700_2.1@63.217,22.135
  Bottom w0.152: X403.1@41.91,51.435 42.604,51.423 43.18,50.847 43.18,37.746 43.4,37.526 v1(43.339,37.465)
SECONDARY-DIGITAL-IO_1: R701_2.1 U700_2.5 X403.2 | length 51.1
  Top w0.152: v1(41.271,37.469) 41.492,37.248 42.772,37.248 43.109,36.911 45.639,36.911 47.625,34.925 47.625,28.455 50.641,25.439 54.797,25.439 55.153,25.082 60.642,25.082 60.956,24.769 60.956,22.357 61.178,22.135 R701_2.1@61.73,22.135 61.73,21.407 61.341,21.018 59.605,21.018 59.245,20.659 59.245,18.986 58.84,18.581 U700_2.5@57.936,18.581
  Bottom w0.152: v1(41.271,37.469) 40.799,37.941 40.799,48.419 41.275,48.895 X403.2@41.91,48.895
SECONDARY-DIGITAL-IO_2: R702_2.1 U700_2.6 X403.3 | length 51.9
  Top w0.152: v1(40.005,37.465) 40.481,36.989 40.481,35.401 40.74,35.142 42.346,35.142 42.446,35.242 46.672,35.242 47.307,34.608 47.307,28.316 50.439,25.185 54.597,25.185 55.017,24.765 59.039,24.765 59.369,24.435 59.369,22.357 59.591,22.135 R702_2.1@60.142,22.135 60.142,21.566 59.849,21.273 59.499,21.273 58.991,20.764 58.991,19.491 58.732,19.231 U700_2.6@57.936,19.231
  Bottom w0.152: X403.3@39.37,51.435 40.005,51.435 40.481,50.959 40.481,37.941 v1(40.005,37.465)
SECONDARY-DIGITAL-IO_3: R703_2.1 U700_2.7 X403.4 | length 48.1
  Top w0.152: v1(38.735,37.465) 38.259,36.989 38.259,35.401 38.772,34.888 42.451,34.888 42.488,34.925 46.355,34.925 46.99,34.29 46.99,28.099 50.158,24.931 54.394,24.931 54.889,24.435 57.464,24.435 57.781,24.118 57.781,22.357 58.003,22.135 R703_2.1@58.555,22.135 58.555,20.979 58.737,20.796 58.737,20.31 58.308,19.881 U700_2.7@57.936,19.881
  Bottom w0.152: v1(38.735,37.465) 38.195,38.005 38.195,48.355 38.735,48.895 X403.4@39.37,48.895
SECONDARY-DIGITAL-IO_4: R704_2.1 U700_2.9 X403.5 | length 52.4
  Top w0.152: v1(37.465,37.465) 37.941,36.989 37.941,34.449 38.1,34.29 38.1,32.703 38.417,32.385 46.355,32.385 46.672,32.067 46.672,27.94 49.936,24.677 54.206,24.677 54.765,24.118 55.876,24.118 56.194,23.8 56.194,22.357 56.416,22.135 R704_2.1@56.967,22.135 56.967,21.249 56.674,20.955 55.245,20.955 54.821,20.531 U700_2.9@52.236,20.531
  Bottom w0.152: X403.5@36.83,51.435 37.465,51.435 37.941,50.959 37.941,37.941 v1(37.465,37.465)
SECONDARY-DIGITAL-IO_5: R705_2.1 U700_2.10 X403.6 | length 49
  Top w0.152: v1(36.195,37.465) 35.719,36.989 35.719,32.544 36.131,32.131 42.037,32.131 49.745,24.423 53.984,24.423 54.606,23.8 54.606,22.357 54.828,22.135 R705_2.1@55.38,22.135 55.38,21.684 54.651,20.955 51.435,20.955 51.276,20.796 51.276,20.14 51.535,19.881 U700_2.10@52.236,19.881
  Bottom w0.152: v1(36.195,37.465) 35.719,37.941 35.719,48.419 36.195,48.895 X403.6@36.83,48.895
SECONDARY-DIGITAL-IO_6: R706_2.1 U700_2.11 X403.7 | length 50.1
  Top w0.152: v1(34.925,37.465) 35.401,36.989 35.401,32.226 35.75,31.877 41.783,31.877 49.542,24.118 52.701,24.118 52.781,24.038 53.019,23.8 53.019,22.357 53.241,22.135 R706_2.1@53.792,22.135 53.792,21.59 53.411,21.209 51.33,21.209 51.022,20.901 51.022,19.621 51.412,19.231 U700_2.11@52.236,19.231
  Bottom w0.152: X403.7@34.29,51.435 34.925,51.435 35.401,50.959 35.401,37.941 v1(34.925,37.465)
SECONDARY-DIGITAL-IO_7: R707_2.1 U700_2.12 X403.8 | length 46.4
  Top w0.152: X403.8@34.29,48.895 33.655,48.895 33.225,48.465 33.225,31.99 33.591,31.623 41.402,31.623 50.89,22.135 R707_2.1@52.205,22.135 52.205,21.684 51.984,21.463 51.225,21.463 50.768,21.007 50.768,19.348 51.535,18.581 U700_2.12@52.236,18.581
SECONDARY-GPIO1-OPT: R1408_2.1 R1425_2.1 X404.6 | length 120.6
  Top w0.152: R1408_2.1@93.093,61.119 v1(93.98,61.119)
  Top w0.203: v1@10.287,29.337 R1425_2.1@10.287,30.161
  Signals1 w0.152: X404.6@24.13,33.655 23.084,33.655 22.86,33.879 22.86,38.1 23.177,38.417 29.21,38.417 29.527,38.735 29.527,52.705 29.845,53.023 40.322,53.023 40.75,53.45 40.75,59.178 40.64,59.287 40.64,60.726 44.349,64.435 93.511,64.435 93.98,63.967 v1(93.98,61.119)
  Signals1 w0.203: v1(10.271,29.337) 12.118,29.337 15.358,32.577 23.052,32.577 X404.6@24.13,33.655
SECONDARY-GPIO2-OPT: R1410_2.1 R1426_2.1 X404.8 | length 129.4
  Top w0.152: R1410_2.1@93.143,56.515 v1(93.98,56.515)
  Top w0.203: v1@8.89,29.337 R1426_2.1@8.89,30.161
  Signals2 w0.203: v1(8.874,29.337) 9.451,29.337 10.335,28.452 14.27,28.452 14.915,29.097 14.915,29.503 15.415,30.004 17.994,30.004 18.11,29.888 18.59,29.888 19.17,30.468 19.17,31.177 21.59,33.597 X404.8@21.59,33.655
  Signals1 w0.152: X404.8@21.59,33.655 20.525,33.655 20.32,33.86 20.32,38.417 20.637,38.735 28.892,38.735 29.21,39.052 29.21,53.023 29.527,53.34 40.005,53.34 40.496,53.831 40.496,59.072 40.322,59.246 40.322,60.768 44.244,64.689 93.743,64.689 94.615,63.817 94.615,56.832 94.297,56.515 v1(93.98,56.515)
SECONDARY-GPIO3-OPT: R1412_2.1 R1427_2.1 X404.10 | length 136
  Top w0.152: R1412_2.1@93.143,53.34 v1(93.98,53.34)
  Top w0.203: v1@7.493,29.337 R1427_2.1@7.493,30.161
  Signals2 w0.203: v1(7.477,29.337) 7.477,29.702 7.874,30.099 11.356,30.099 12.698,28.757 13.178,28.757 13.589,29.168 13.589,29.972 14.293,30.676 17.114,30.676 17.911,31.474 17.911,32.262 19.177,33.528 X404.10@19.05,33.655
  Signals1 w0.152: X404.10@19.05,33.655 18.029,33.655 17.78,33.904 17.78,38.735 18.098,39.052 28.575,39.052 28.892,39.37 28.892,53.34 29.21,53.657 39.688,53.657 40.242,54.212 40.242,58.967 40.005,59.204 40.005,60.809 44.139,64.943 94.124,64.943 94.932,64.135 94.932,53.657 94.615,53.34 v1(93.98,53.34)
SECONDARY-GPIO4-OPT: R1414_2.1 X404.12 | length 125.2
  Top w0.152: R1414_2.1@93.093,50.165 93.093,50.265 93.463,50.636 93.498,50.636 v1(93.98,51.117) ; R1414_2.1@93.143,50.165 R1414_2.1@93.143,50.166
  Signals1 w0.152: X404.12@16.51,33.655 15.425,33.655 15.24,33.84 15.24,39.052 15.557,39.37 28.258,39.37 28.575,39.688 28.575,53.657 28.892,53.975 39.37,53.975 39.688,54.292 39.688,57.953 39.133,58.508 39.133,58.967 39.688,59.522 39.688,60.851 44.034,65.197 94.229,65.197 95.204,64.223 95.204,52.341 v1(93.98,51.117)
SECONDARY-GPIO5-OPT: R1416_2.1 X404.14 | length 131
  Top w0.152: R1416_2.1@93.072,46.97 93.072,47.678 93.337,47.942 v1(93.821,47.942) ; R1416_2.1@93.14,47.099 R1416_2.1@93.143,46.99
  Signals1 w0.152: X404.14@13.97,33.655 12.945,33.655 12.7,33.9 12.7,39.37 13.018,39.688 27.94,39.688 28.258,40.005 28.258,53.975 28.575,54.292 38.1,54.292 38.879,55.072 38.879,59.072 39.37,59.563 39.37,60.893 43.929,65.451 94.335,65.451 95.458,64.328 95.458,63.377 95.467,63.368 95.467,49.513 93.897,47.942 v1(93.821,47.942)
SECONDARY-GPIO6: IC1400_2.44 R1421_2.1 X405.2 | length 113.7
  Top w0.152: R1421_2.1@75.63,53.721 75.63,53.821 76.454,54.645 v1(76.454,54.737) ; IC1400_2.44@88.618,51.598 90.015,51.598 v1(90.17,51.752)
  Signals1 w0.152: X405.2@41.91,33.655 43.497,33.655 43.893,34.051 43.893,40.413 43.578,40.728 43.578,41.153 43.561,41.17 43.561,62.928 44.56,63.927 91.33,63.927 92.392,62.865 92.392,51.435 92.075,51.117 90.805,51.117 v1(90.17,51.752)
  Bottom w0.152: v1(76.454,54.737) 77.47,55.753 86.169,55.753 v1(90.17,51.752)
SECONDARY-GPIO7: IC1400_2.45 R1422_2.1 X405.4 | length 114.9
  Top w0.152: R1422_2.1@75.63,55.118 75.63,55.218 76.001,55.589 76.29,55.589 v1(76.327,55.626) ; IC1400_2.45@88.618,52.097 89.731,52.097 90.137,52.504 v1(90.65,52.504)
  Signals2 w0.152: X405.4@39.37,33.655 40.64,32.385 43.815,32.385 44.133,32.703 v1(44.133,40.957)
  Signals1 w0.152: v1(44.133,40.957) 43.815,41.275 43.815,62.547 44.941,63.673 90.949,63.673 92.075,62.547 92.075,52.938 91.641,52.504 v1(90.65,52.504)
  Bottom w0.152: v1(76.327,55.626) 76.708,56.007 87.147,56.007 v1(90.65,52.504)
SECONDARY-GPIO8: IC1400_2.46 R1423_2.1 X405.6 | length 116.1
  Top w0.152: R1423_2.1@75.63,56.515 76.327,56.515 v1(76.327,56.468) ; IC1400_2.46@88.618,52.598 89.745,52.598 90.404,53.257 v1(90.835,53.257)
  Signals2 w0.152: X405.6@36.83,33.655 38.417,32.067 44.45,32.067 44.767,32.385 v1(44.767,41.593)
  Signals1 w0.152: v1(44.767,41.593) 44.133,42.227 44.133,62.23 45.322,63.419 90.568,63.419 91.757,62.23 91.757,53.809 91.206,53.257 v1(90.835,53.257)
  Bottom w0.152: v1(76.327,56.468) 76.52,56.275 87.404,56.275 90.421,53.257 v1(90.835,53.257)
SECONDARY-GPIO9: IC1400_2.47 R1424_2.1 X405.8 | length 102.3
  Top w0.152: IC1400_2.47@88.618,53.097 89.61,53.097 v1(90.487,53.975) 90.051,53.975 89.725,54.301 R1424_2.1@89.725,54.752
  Signals2 w0.152: X405.8@34.29,33.655 36.195,31.75 45.085,31.75 45.402,32.067 v1(45.402,40.957)
  Signals1 w0.152: v1(45.402,40.957) 45.402,41.91 44.45,42.862 44.45,61.912 44.767,62.23 68.678,62.23 68.965,61.943 69.465,61.943 70.307,62.784 75.795,62.784 76.349,62.23 76.686,62.23 77.003,61.912 91.013,61.912 91.44,61.485 91.44,54.292 91.123,53.975 v1(90.487,53.975)
SECONDARY-IN+: TP1405_2.1 TR1400_2.4 X502.1 | length 17.4
  Top w0.254: TR1400_2.4@23.086,13.738 23.827,13.738 24.13,13.434 24.13,12.803 24.447,12.485 31.012,12.485 32.544,10.954 TP1405_2.1@33.387,10.954 33.387,7.144 33.713,6.818 X502.1@35,6.818
SECONDARY-IN-: TP1404_2.1 TR1400_2.6 X502.2 | length 11.9
  Top w0.254: TR1400_2.6@27.099,13.738 30.712,13.738 32.669,11.781 34.574,11.781 35,11.355 35,10.954 ; X502.2@35,9.815 35,10.954 ; TP1404_2.1@36.512,10.954 35,10.954
SECONDARY-LTC-DRIVE: IC1400_2.49 R605_2.1 R610_2.2 | length 47.3
  Top w0.152: R605_2.1@53.975,43.115 55.073,43.115 55.245,43.287 R610_2.2@55.245,45.02 55.945,45.02 v1(56.197,44.767) ; v1(78.105,54.927) 78.105,54.05 79.132,53.023 85.557,53.023 86.618,54.083 IC1400_2.49@86.618,55.547 ; IC1400_2.49@86.618,55.598 IC1400_2.49@86.653,55.562
  Signals1 w0.152: v1(56.197,44.767) 56.515,44.45 58.039,44.45 76.2,44.45 77.8,46.05 77.8,53.647 78.105,53.951 v1(78.105,54.927)
SECONDARY-MUX-DATA_TEMP: C106_2.2 R108_2.2 R1409_2.1 | length 53
  Top w0.254: R108_2.2@77.059,24.606 77.059,24.506 78.387,23.177 v1(78.74,23.177) ; C106_2.2@93.117,59.69 93.117,59.113 93.093,59.088 R1409_2.1@93.093,58.261 93.814,58.261 v1(93.833,58.281)
  Signals2 w0.254: v1(78.74,23.177) 78.74,51.752 80.04,53.052 82.262,53.052 83.185,53.975 83.185,57.053 84.839,58.708 93.406,58.708 v1(93.833,58.281)
SECONDARY-MUX-DATA_USER: C107_2.2 R109_2.2 R1411_2.1 | length 80.9
  Top w0.152: R109_2.2@26.447,58.725 28.008,58.725 C107_2.2@28.147,58.728 ; C107_2.2@28.147,58.725 28.701,58.725 28.892,58.916 28.892,59.69 v1(29.21,60.008) ; R1411_2.1@93.093,55.086 93.544,55.086 93.703,55.245 v1(93.98,55.245) v1@93.833,55.106
  Signals2 w0.152: v1(29.21,60.008) 29.527,59.69 35.369,59.69 35.543,59.863 36.212,59.863 36.877,59.199 38.647,59.199 39.247,59.8 39.797,59.8 42.227,62.23 68.678,62.23 68.965,61.943 69.465,61.943 70.307,62.784 75.795,62.784 76.349,62.23 76.686,62.23 76.923,61.993 77.7,61.993 78.173,62.467 94.196,62.467 94.932,61.73 94.932,55.562 94.615,55.245 v1(93.98,55.245)
SECONDARY-OUT+: TP1406_2.1 TR1400_2.1 X503.1 | length 16.4
  Top w0.254: TR1400_2.1@17.066,13.738 17.794,13.738 18.098,13.434 18.098,11.906 18.574,11.43 24.359,11.43 24.835,10.954 TP1406_2.1@25.717,10.954 25.717,7.144 26.043,6.818 X503.1@27.5,6.818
